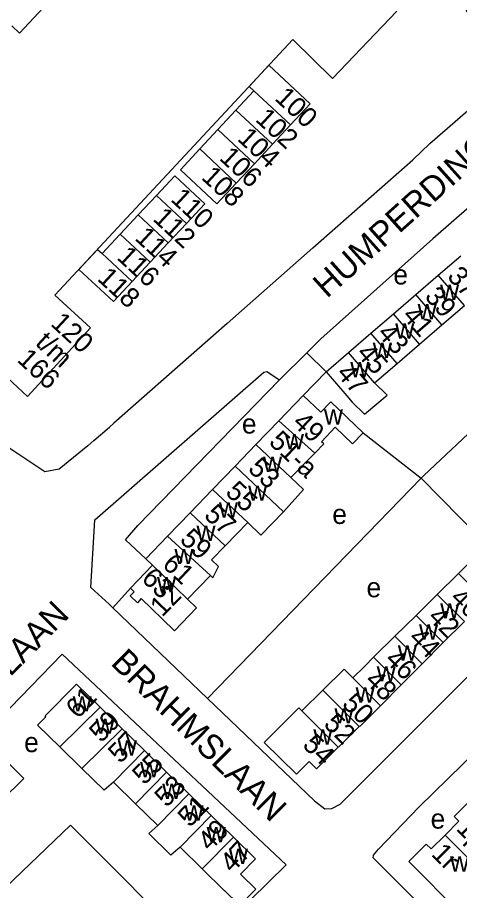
# Model space of a CAD drawing. Extents: x 159045 to 160918, y 380454 to 382516.
# Drawn here: x 159933.2 to 160022.9, y 381769.4 to 381946.6 of the extents above; entities that cross this region are included whole.
import ezdxf

# ---------------------------------------------------------------- set-up
doc = ezdxf.new("R2010")
doc.units = 0
for name, color, linetype in [('BLT_Basislijn', 7, 'Continuous'), ('BLT_Bebouwing', 7, 'Continuous'), ('BLT_Centroide', 7, 'Continuous'), ('BLT_Huisnummer', 7, 'Continuous'), ('BLT_Huisnummer_ tussenligend', 7, 'Continuous'), ('BLT_Huisnummer_reeks', 7, 'Continuous'), ('BLT_Huisnummer_zonder_bebouwing', 7, 'Continuous'), ('BLT_Onderverdeling_panden', 7, 'Continuous'), ('BLT_Plantopo', 7, 'Continuous'), ('BLT_Straatnaam', 7, 'Continuous')]:
    doc.layers.add(name, color=color, linetype=linetype)

msp = doc.modelspace()

# ---------------------------------------------------------------- linework, layer by layer
at = {"layer": 'BLT_Basislijn'}
for p, q in [((159975.69, 381884.47), (159993.1, 381899.81)), ((159975.69, 381884.47), (159952.7, 381864.23)), ((159986.32, 381873.03), (159991.89, 381878.48)), ((159991.89, 381878.48), (159995.78, 381874.67)), ((159995.78, 381874.67), (159991.15, 381869.85)), ((160003.3, 381862.23), (160015.06, 381853.05)), ((159971.73, 381808.32), (160015.06, 381853.05)), ((160015.06, 381853.05), (160030.98, 381836.86)), ((159956.07, 381830.73), (159952.5, 381826.77)), ((159971.73, 381808.32), (159952.5, 381826.77))]:
    msp.add_line(p, q, dxfattribs=at)
for points in [[(159993.1, 381899.81), (160013.35, 381917.65), (160016.8, 381920.99), (160045.62, 381945.99)], [(160032.86, 381915.12), (160017.42, 381901.61), (159994.74, 381881.31), (159991.89, 381878.48)], [(160015.06, 381853.05), (160015.6, 381853.61), (160053.82, 381889.54), (160054.51, 381890.45)], [(159948.66, 381860.71), (159947.44, 381859.65), (159941.62, 381854.9), (159938.73, 381854.35), (159924.83, 381863.57), (159910.44, 381873.44)], [(159952.5, 381826.77), (159951.75, 381827.49), (159948.06, 381830.86), (159948.89, 381844.6), (159983.13, 381874.55), (159983.78, 381874.74), (159986.32, 381873.03)], [(159959.18, 381836.71), (159955.05, 381840.55), (159957.6, 381843.48), (159986.32, 381873.03)], [(159948.66, 381860.71), (159951.8, 381863.44), (159952.7, 381864.23)], [(159971.73, 381808.32), (159993.45, 381787.59), (159995.51, 381785.97), (159996.96, 381786.04), (159998.62, 381786.91), (160039.76, 381828.03)], [(159969.6, 381756.85), (159987.65, 381774.62), (159942.26, 381817.34), (159906.31, 381780.37)], [(160031.42, 381750), (160005.33, 381776.02), (160005.42, 381776.59), (160006.44, 381777.77), (160014.6, 381786.33), (160026.49, 381797.96), (160027.1, 381798.56)], [(159924.2, 381763.75), (159943.93, 381782.66), (159969.6, 381756.85)]]:
    msp.add_lwpolyline(points, dxfattribs=at)
at = {"layer": 'BLT_Bebouwing'}
for p, q in [((160018.54, 381894.27), (160023.1, 381898.18)), ((160013.99, 381890.34), (160018.54, 381894.27)), ((160009.43, 381886.42), (160013.99, 381890.34)), ((160019.28, 381884.2), (160023.83, 381888.12)), ((160004.87, 381882.5), (160009.43, 381886.42)), ((160014.72, 381880.28), (160019.28, 381884.2)), ((160000.32, 381878.58), (160004.87, 381882.5)), ((160010.17, 381876.36), (160014.72, 381880.28)), ((159995.78, 381874.67), (160000.32, 381878.58)), ((160005.61, 381872.43), (160010.17, 381876.36)), ((159986.19, 381864.7), (159991.15, 381869.85)), ((159981.54, 381859.88), (159986.19, 381864.7)), ((159977.3, 381855.49), (159981.54, 381859.88)), ((159988.66, 381853.19), (159993.49, 381858.14)), ((159972.74, 381850.77), (159977.3, 381855.49)), ((159968.19, 381846.05), (159972.74, 381850.77)), ((159963.63, 381841.32), (159968.19, 381846.05)), ((159975.31, 381839.35), (159979.87, 381844.07)), ((159959.18, 381836.71), (159963.63, 381841.32)), ((160022.64, 381833.71), (160026.95, 381837.96)), ((159960.56, 381835.38), (159959.18, 381836.71)), ((159956.07, 381830.73), (159960.56, 381835.38)), ((159967.67, 381828.52), (159972.3, 381833.33)), ((160018.34, 381829.46), (160022.64, 381833.71)), ((160014.03, 381825.22), (160018.34, 381829.46)), ((160009.73, 381820.97), (160014.03, 381825.22)), ((160023.83, 381823.96), (160019.55, 381819.68)), ((160005.42, 381816.72), (160009.73, 381820.97)), ((160019.55, 381819.68), (160015.27, 381815.41)), ((160015.27, 381815.41), (160010.98, 381811.14)), ((159945.11, 381811.29), (159949.91, 381806.61)), ((159990.87, 381805.83), (159995.13, 381810.04)), ((160010.98, 381811.14), (160006.84, 381806.87)), ((159949.91, 381806.61), (159954.42, 381802.21)), ((159954.42, 381802.21), (159958.93, 381797.81)), ((159946.25, 381794.15), (159941.74, 381798.55)), ((159958.93, 381797.81), (159963.43, 381793.41)), ((159963.43, 381793.41), (159967.94, 381789.01)), ((159957.12, 381786.95), (159952.62, 381791.35)), ((159967.94, 381789.01), (159972.45, 381784.61)), ((159961.63, 381782.55), (159957.12, 381786.95)), ((159972.45, 381784.61), (159976.96, 381780.21)), ((159970.65, 381773.75), (159966.14, 381778.15))]:
    msp.add_line(p, q, dxfattribs=at)
for points in [[(159995.78, 381874.67), (160000.01, 381869.75), (160001.06, 381868.51), (160003.55, 381866.05), (160008.17, 381869.93), (160005.61, 381872.43)], [(159991.15, 381869.85), (159994.7, 381866.43), (159996.73, 381868.53), (160003.3, 381862.23)], [(159993.49, 381858.14), (159995.29, 381860), (159994.82, 381860.45), (159997.65, 381863.38), (160001.16, 381860), (160003.3, 381862.23)], [(159987.12, 381846.26), (159991.2, 381850.74), (159988.66, 381853.19)], [(159979.87, 381844.07), (159982.53, 381841.5), (159987.12, 381846.26)], [(159972.3, 381833.33), (159972.78, 381832.86), (159973.98, 381835.11), (159972.55, 381836.49), (159975.31, 381839.35)], [(159967.67, 381828.52), (159969.5, 381826.73), (159965.04, 381822.1), (159962.61, 381824.44), (159958.28, 381828.61), (159957.49, 381827.79), (159956.04, 381829.18), (159956.83, 381830), (159956.07, 381830.73)], [(160001.23, 381812.52), (160003.54, 381814.86), (160005.42, 381816.72)], [(159995.13, 381810.04), (159999.42, 381814.29), (160001.23, 381812.52)], [(159941.74, 381798.55), (159937.23, 381802.94), (159938.9, 381804.66), (159938.81, 381804.83), (159945.11, 381811.29)], [(159998.24, 381798.44), (159993.85, 381794.06), (159992.35, 381795.56), (159989.76, 381792.98), (159983.21, 381799.39), (159990.27, 381806.43), (159990.87, 381805.83)], [(160006.84, 381806.87), (160002.69, 381802.73), (160002.51, 381802.65)], [(160002.51, 381802.65), (159998.39, 381798.52), (159998.24, 381798.44)], [(159923.51, 381793.99), (159928.04, 381798.51), (159934.42, 381792.11), (159929.98, 381787.69)], [(159952.62, 381791.35), (159950.77, 381789.75), (159946.25, 381794.15)], [(160026.28, 381786.95), (160025.3, 381787.95), (160021.75, 381784.42), (160022.73, 381783.43), (160019.91, 381780.63)], [(159966.14, 381778.15), (159964.3, 381776.56), (159959.79, 381780.96), (159961.63, 381782.55)], [(159976.96, 381780.21), (159981.47, 381775.83), (159978.42, 381772.7), (159981.52, 381769.67)], [(160019.91, 381780.63), (160017.09, 381777.83), (160016.11, 381778.82), (160012.56, 381775.3), (160022.94, 381764.85)], [(159981.52, 381769.67), (159978.1, 381766.16), (159977.84, 381766.41), (159978.04, 381766.62), (159975.2, 381769.39), (159975.15, 381769.34), (159970.65, 381773.75)]]:
    msp.add_lwpolyline(points, dxfattribs=at)
at = {"layer": 'BLT_Onderverdeling_panden'}
for p, q in [((160023.83, 381888.12), (160018.54, 381894.27)), ((160019.28, 381884.2), (160013.99, 381890.34)), ((160014.72, 381880.28), (160009.43, 381886.42)), ((160010.17, 381876.36), (160004.87, 381882.5)), ((160005.61, 381872.43), (160000.32, 381878.58)), ((159993.49, 381858.14), (159986.19, 381864.7)), ((159988.66, 381853.19), (159981.54, 381859.88)), ((159987.12, 381846.26), (159977.3, 381855.49)), ((159979.87, 381844.07), (159972.74, 381850.77)), ((159975.31, 381839.35), (159968.19, 381846.05)), ((159972.3, 381833.33), (159963.63, 381841.32)), ((159960.56, 381835.38), (159967.67, 381828.52)), ((160028.11, 381828.23), (160022.64, 381833.71)), ((160023.83, 381823.96), (160018.34, 381829.46)), ((160019.55, 381819.68), (160014.03, 381825.22)), ((160015.27, 381815.41), (160009.73, 381820.97)), ((160010.98, 381811.14), (160005.42, 381816.72)), ((160006.84, 381806.87), (160001.23, 381812.52)), ((160002.51, 381802.65), (159995.13, 381810.04)), ((159941.74, 381798.55), (159949.91, 381806.61)), ((159998.24, 381798.44), (159990.87, 381805.83)), ((159946.25, 381794.15), (159954.42, 381802.21)), ((159952.62, 381791.35), (159958.93, 381797.81)), ((159957.12, 381786.95), (159963.43, 381793.41)), ((159961.63, 381782.55), (159967.94, 381789.01)), ((159966.14, 381778.15), (159972.45, 381784.61)), ((159970.65, 381773.75), (159976.96, 381780.21)), ((160029.31, 381771.17), (160019.91, 381780.63))]:
    msp.add_line(p, q, dxfattribs=at)
at = {"layer": 'BLT_Plantopo'}
for p, q in [((159933.59, 381943.37), (159959.76, 381971.53)), ((160010.13, 381947.82), (159997.11, 381934.19)), ((159932.02, 381944.83), (159933.59, 381943.37)), ((159989, 381942.1), (159940.72, 381890.21)), ((159997.11, 381934.19), (159989, 381942.1)), ((159980.17, 381932.57), (159984.15, 381936.84)), ((159984.15, 381936.84), (159992.55, 381929.01)), ((159981.15, 381931.65), (159977.5, 381927.73)), ((159981.15, 381931.65), (159980.17, 381932.57)), ((159988.56, 381924.74), (159981.15, 381931.65)), ((159992.55, 381929.01), (159988.56, 381924.74)), ((159973.82, 381923.79), (159977.5, 381927.73)), ((159977.5, 381927.73), (159984.9, 381920.82)), ((159984.9, 381920.82), (159988.56, 381924.74)), ((159973.82, 381923.79), (159970.16, 381919.86)), ((159981.23, 381916.88), (159973.82, 381923.79)), ((159966.21, 381915.64), (159970.16, 381919.86)), ((159970.16, 381919.86), (159977.56, 381912.95)), ((159984.9, 381920.82), (159981.23, 381916.88)), ((159977.56, 381912.95), (159981.23, 381916.88)), ((159961.35, 381910.45), (159965.06, 381914.44)), ((159965.06, 381914.44), (159971.16, 381908.76)), ((159973.62, 381908.73), (159966.21, 381915.64)), ((159977.56, 381912.95), (159973.62, 381908.73)), ((159961.35, 381910.45), (159957.67, 381906.5)), ((159967.44, 381904.77), (159961.35, 381910.45)), ((159971.16, 381908.76), (159967.44, 381904.77)), ((159935.17, 381869.65), (159896.03, 381906.17)), ((159954, 381902.57), (159957.67, 381906.5)), ((159957.67, 381906.5), (159963.76, 381900.82)), ((159963.76, 381900.82), (159967.44, 381904.77)), ((159954, 381902.57), (159950.32, 381898.62)), ((159960.1, 381896.89), (159954, 381902.57)), ((159963.76, 381900.82), (159960.1, 381896.89)), ((159945.61, 381895.44), (159949.39, 381899.49)), ((159949.39, 381899.49), (159950.32, 381898.62)), ((159950.32, 381898.62), (159956.41, 381892.94)), ((159956.41, 381892.94), (159960.1, 381896.89)), ((159952.64, 381888.89), (159945.61, 381895.44)), ((159956.41, 381892.94), (159952.64, 381888.89)), ((159940.72, 381890.21), (159947.96, 381883.55)), ((159947.96, 381883.55), (159935.17, 381869.65))]:
    msp.add_line(p, q, dxfattribs=at)

# ---------------------------------------------------------------- texts
at = {"layer": 'BLT_Centroide'}
for s, p in [('e', (160009.43, 381892.37)), ('w', (160018.91, 381889.23)), ('w', (160014.36, 381885.3)), ('w', (160009.8, 381881.39)), ('w', (160005.25, 381877.47)), ('w', (160000.69, 381873.55)), ('w', (159995.34, 381863.94)), ('e', (159978.7, 381862.11)), ('w', (159987.42, 381858.94)), ('w', (159982.98, 381854.34)), ('w', (159979.95, 381848.5)), ('w', (159974.03, 381845.06)), ('e', (159997.04, 381843.77)), ('w', (159969.48, 381840.34)), ('w', (159965.01, 381835.62)), ('w', (159961.47, 381829.91)), ('e', (160003.98, 381828.89)), ('w', (160018.94, 381824.59)), ('w', (160014.64, 381820.31)), ('w', (160010.34, 381816.06)), ('w', (160006.05, 381811.81)), ('w', (160001.77, 381807.53)), ('w', (159944.36, 381805.73)), ('w', (159997.48, 381803.28)), ('w', (159949.02, 381801.19)), ('e', (159934.51, 381797.47)), ('w', (159993.2, 381799)), ('w', (159953.52, 381796.78)), ('w', (159958.03, 381792.38)), ('w', (159962.53, 381787.98)), ('w', (159967.05, 381783.58)), ('e', (160016.99, 381781.94)), ('w', (159971.55, 381779.17)), ('w', (159976.06, 381774.78)), ('w', (160020.94, 381773.23))]:
    msp.add_text(s, height=4, dxfattribs=at).set_placement(p)
at = {"layer": 'BLT_Huisnummer'}
for s, rotation, p in [('37', 310.7193, (160020.18, 381893.91)), ('41', 310.7201, (160011.05, 381885.92)), ('47', 310.7018, (159997.69, 381874.21)), ('49', 316.7821, (159988.75, 381864.06)), ('53', 316.7875, (159979.73, 381854.73)), ('57', 316.7848, (159970.81, 381845.27)), ('42', 314.9222, (160016.22, 381824.62)), ('46', 314.9229, (160007.52, 381816.03)), ('61', 45.6865, (159945.42, 381804.08)), ('50', 314.9233, (159998.81, 381807.03)), ('54', 314.9232, (159990.81, 381798.72)), ('55', 45.6865, (159958.9, 381790.63)), ('51', 45.6865, (159968.12, 381782.03)), ('1p', 314.8051, (160022, 381781.78)), ('47', 45.6865, (159976.71, 381772.78)), ('1r', 314.8063, (160016.97, 381776.61))]:
    msp.add_text(s, height=4, rotation=rotation, dxfattribs=at).set_placement(p)
at = {"layer": 'BLT_Huisnummer_ tussenligend'}
for s, rotation, p in [('39', 310.7193, (160015.61, 381889.83)), ('43', 310.7201, (160006, 381882.36)), ('45', 310.7201, (160001.76, 381878.29)), ('55', 316.7875, (159975.15, 381849.97)), ('59', 316.7848, (159965.9, 381840.35)), ('61', 316.7848, (159962.33, 381835.28)), ('40', 314.9219, (160020.72, 381828.49)), ('44', 314.9222, (160012.31, 381820.39)), ('48', 314.9229, (160003.45, 381811.78)), ('59', 45.6865, (159950.15, 381799.21)), ('52', 314.9233, (159995.09, 381802.95)), ('57', 45.6865, (159954.01, 381794.99)), ('53', 45.6865, (159963.43, 381786.09)), ('49', 45.6865, (159972.18, 381777.16))]:
    msp.add_text(s, height=4, rotation=rotation, dxfattribs=at).set_placement(p)
at = {"layer": 'BLT_Huisnummer_reeks'}
for s, rotation, p in [('51-a', 316.7821, (159983.97, 381860.17)), ('63', 316.0311, (159958.12, 381832.44)), ('12', 46.0128, (159962.54, 381824.73))]:
    msp.add_text(s, height=4, rotation=rotation, dxfattribs=at).set_placement(p)
at = {"layer": 'BLT_Huisnummer_zonder_bebouwing'}
for s, p in [('100', (159985.17, 381929.94)), ('102', (159981.24, 381925.67)), ('104', (159977.58, 381921.75)), ('106', (159973.93, 381917.82)), ('108', (159970.29, 381913.89)), ('110', (159964.07, 381909.44)), ('112', (159960.43, 381905.5)), ('114', (159956.77, 381901.58)), ('116', (159953.13, 381897.65)), ('118', (159949.16, 381893.36)), ('120', (159939.69, 381884.21)), ('t/m', (159936.58, 381880.27)), ('166', (159932.89, 381876.88))]:
    msp.add_text(s, height=4, rotation=317.1442, dxfattribs=at).set_placement(p)
at = {"layer": 'BLT_Straatnaam'}
for s, rotation, p in [('HENRIETTE BOSMANSPAD', 317.5775, (159972.47, 381994.93)), ('HUMPERDINCKLAAN', 41.8592, (159995.94, 381889.42)), ('OFFENBACHLAAN', 45.4522, (159902.76, 381783.24)), ('BRAHMSLAAN', 315.4166, (159951.88, 381815.35)), ('MASSENETSTRAAT', 317.411, (159903.18, 381775.46))]:
    msp.add_text(s, height=5, rotation=rotation, dxfattribs=at).set_placement(p)

doc.saveas('drawing.dxf')
